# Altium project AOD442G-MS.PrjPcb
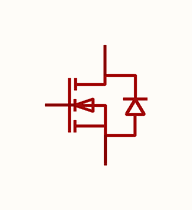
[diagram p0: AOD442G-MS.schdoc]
1 sheet, 1 parts. Net scope: global (net labels, ports and power ports of the same name join across sheets).

## Sheet AOD442G-MS.schdoc
size 127 x 101 mm

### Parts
Q?  aod442g-ms  [TO-252-3_L6.6-W6.1-P4.57-LS9.9-BR-CW]  (value not drawn)

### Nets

Not connected (* = marked no-connect by the designer): Q? 1(G) 2(D) 3(S)

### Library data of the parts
Q? = aod442g-ms: 数量:1个N沟道;漏源电压(Vdss):60V;连续漏极电流(Id):50A;导通电阻(RDS(on)):11mΩ@10V;耗散功率(Pd):45W;阈值电压(Vgs(th)):2.5V;; Manufacturer: MSKSEMI(美森科); AddInBom: yes; ModelId: dee852f3c6b348a2b9d5be5dd3244081; ModelTransform: 258.97184,390.1567,0,90,0,0,-35.433,0,0; Number: 1个N沟道; Drain to Source Voltage: 60V; Current - Continuous Drain(Id): 50A; Pd - Power Dissipation: 45W; Gate Threshold Voltage (Vgs(th)): 2.5V; Gate Charge(Qg): 19.3nC@4.5V; Input Capacitance(Ciss): 2.423nF; Reverse Transfer Capacitance (Crss@Vds): 97pF; Type: N沟道; Output Capacitance(Coss): 145pF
